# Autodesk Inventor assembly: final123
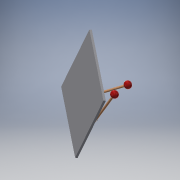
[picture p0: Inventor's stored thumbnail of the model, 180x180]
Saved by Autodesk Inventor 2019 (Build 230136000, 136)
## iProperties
Created: 2020-02
Part Number: final123
Document SubType Name: Assembly
Designer: ash
Author: ash
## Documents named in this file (11)
- F:\autodesk\FINAL (2).iam
- F:\autodesk\Assembly1.iam
- C:\Users\ash\Downloads\Servo-MG90S (1).ipt
- F:\autodesk\clip.ipt
- F:\autodesk\holder.ipt
- F:\autodesk\stick.ipt
- F:\autodesk\Xylo_base.ipt
- F:\autodesk\new_base_holder.ipt
- F:\autodesk\clamp.ipt
- F:\autodesk\fnut.ipt
- F:\autodesk\fboalt.ipt
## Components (28 placed, 10 different names)
1. Assembly1:1 [sub-assembly] — Mate:11, Mate:12, Tangent:3, Mate:16, Mate:17
2. Assembly1:2 [sub-assembly] — Mate:13, Mate:14, Tangent:2, Mate:15, Mate:18
3. Servo-MG90S (1):1 — Mate:7, Mate:8, Mate:28, Mate:29, Mate:30
4. Servo-MG90S (1):2 — Mate:9, Mate:10, Mate:25, Mate:26, Mate:27
5. clip:1 — Mate:9, Mate:10, Mate:11, Mate:12, Tangent:3
6. clip:2 — Mate:7, Mate:8, Mate:13, Mate:14, Tangent:2
7. holder:1 — Mate:15, Mate:18, Mate:21, Flush:1
8. holder:2 — Mate:16, Mate:17, Mate:19, Mate:20
9. stick:1 — Mate:21, Flush:1
10. stick:2 — Mate:19, Mate:20
11. Xylo_base:1 — Mate:22, Mate:23, Mate:24, Insert:1, Insert:5, Mate:35, Mate:36, Insert:11
12. new_base_holder:1 — Mate:22, Mate:23, Mate:24, Mate:25, Mate:26, Mate:27, Mate:28, Mate:29, Mate:30, Flush:2, Insert:3, Insert:6, Mate:38, Insert:12
13. clamp:1 — Insert:7, Mate:36, Insert:8
14. clamp:2 — Insert:4, Insert:5, Mate:33, Mate:34
15. clamp:3 — Mate:31, Mate:32, Insert:1, Flush:2, Insert:2
16. clamp:4 — Insert:9, Insert:10, Insert:11, Insert:12
17. fnut:1 — Insert:2
18. fnut:2 — Mate:33, Mate:34, Mate:40
19. fnut:3 — Mate:31, Mate:32
20. fnut:4 — Insert:4
21. fboalt:1 — Insert:3
22. fboalt:3 — Mate:37, Mate:38
23. fboalt:4 — Mate:39
24. fboalt:5 — Insert:6, Mate:40
25. fnut:5 — Insert:10, Mate:39
26. fnut:6 — Insert:7, Mate:35
27. fnut:7 — Insert:9
28. fnut:8 — Insert:8, Mate:37
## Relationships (50: Mate 34, Insert 12, Tangent 2, Flush 2)
- Mate:7: Servo-MG90S (1):1 ↔ clip:2
- Mate:8: Servo-MG90S (1):1 ↔ clip:2
- Mate:9: Servo-MG90S (1):2 ↔ clip:1
- Mate:10: Servo-MG90S (1):2 ↔ clip:1
- Mate:11: Assembly1:1 ↔ clip:1
- Mate:12: Assembly1:1 ↔ clip:1
- Mate:13: Assembly1:2 ↔ clip:2
- Mate:14: Assembly1:2 ↔ clip:2
- Tangent:2: Assembly1:2 ↔ clip:2
- Tangent:3: Assembly1:1 ↔ clip:1
- Mate:15: Assembly1:2 ↔ holder:1
- Mate:16: Assembly1:1 ↔ holder:2
- Mate:17: Assembly1:1 ↔ holder:2
- Mate:18: Assembly1:2 ↔ holder:1
- Mate:19: holder:2 ↔ stick:2
- Mate:20: holder:2 ↔ stick:2
- Mate:21: holder:1 ↔ stick:1
- Flush:1: holder:1 ↔ stick:1
- Mate:22: Xylo_base:1 ↔ new_base_holder:1
- Mate:23: Xylo_base:1 ↔ new_base_holder:1
- Mate:24: Xylo_base:1 ↔ new_base_holder:1
- Mate:25: Servo-MG90S (1):2 ↔ new_base_holder:1
- Mate:26: Servo-MG90S (1):2 ↔ new_base_holder:1
- Mate:27: Servo-MG90S (1):2 ↔ new_base_holder:1
- Mate:28: Servo-MG90S (1):1 ↔ new_base_holder:1
- Mate:29: Servo-MG90S (1):1 ↔ new_base_holder:1
- Mate:30: Servo-MG90S (1):1 ↔ new_base_holder:1
- Mate:31: clamp:3 ↔ fnut:3
- Mate:32: clamp:3 ↔ fnut:3
- Insert:1: Xylo_base:1 ↔ clamp:3
- Flush:2: new_base_holder:1 ↔ clamp:3
- Insert:2: clamp:3 ↔ fnut:1
- Insert:3: new_base_holder:1 ↔ fboalt:1
- Insert:4: clamp:2 ↔ fnut:4
- Insert:5: Xylo_base:1 ↔ clamp:2
- Mate:33: clamp:2 ↔ fnut:2
- Mate:34: clamp:2 ↔ fnut:2
- Insert:6: new_base_holder:1 ↔ fboalt:5
- Insert:7: clamp:1 ↔ fnut:6
- Mate:35: Xylo_base:1 ↔ fnut:6
- Mate:36: Xylo_base:1 ↔ clamp:1
- Insert:8: clamp:1 ↔ fnut:8
- Mate:37: fboalt:3 ↔ fnut:8
- Mate:38: new_base_holder:1 ↔ fboalt:3
- Insert:9: clamp:4 ↔ fnut:7
- Insert:10: clamp:4 ↔ fnut:5
- Insert:11: Xylo_base:1 ↔ clamp:4
- Insert:12: new_base_holder:1 ↔ clamp:4
- Mate:39: fboalt:4 ↔ fnut:5
- Mate:40: fnut:2 ↔ fboalt:5
